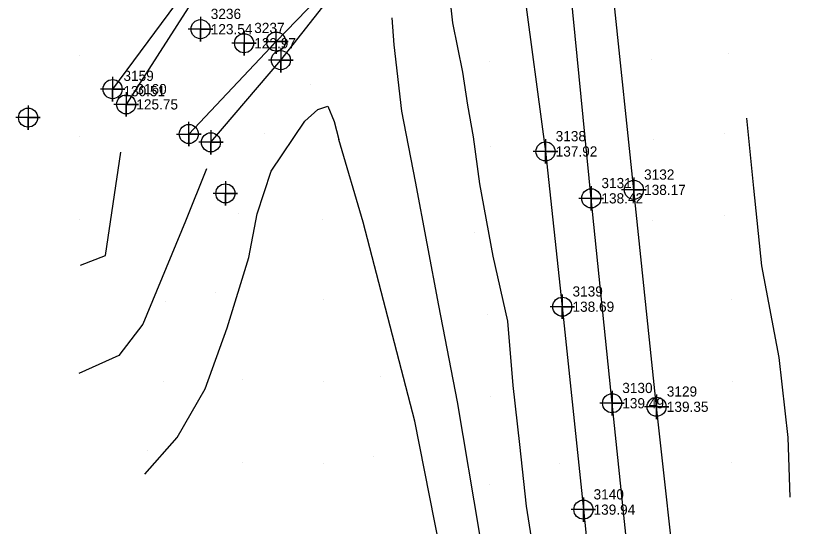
# Model space of a CAD drawing. Extents: x 2312183 to 2312663, y 819676 to 820746.
# Drawn here: x 2312350.8 to 2312544.8, y 819940.8 to 820065.9 of the extents above; entities that cross this region are included whole.
import ezdxf

# ---------------------------------------------------------------- set-up
doc = ezdxf.new("R2010")
doc.units = 0
for name, color, linetype in [('Exist DTM Breakline', 7, 'Continuous'), ('Exist DTM Breakline Cogo Point CELL', 7, 'Continuous'), ('Exist DTM Crownline', 7, 'Continuous'), ('Exist DTM Crownline Cogo Elevation', 7, 'Continuous'), ('Exist DTM Crownline Cogo Number', 7, 'Continuous'), ('Exist DTM Crownline Cogo Point CELL', 7, 'Continuous'), ('Exist DTM Regular Point CELL', 7, 'Continuous'), ('Exist DTM Regular Point Cogo Elevation', 7, 'Continuous'), ('Exist DTM Regular Point Cogo Number', 7, 'Continuous'), ('Exist DTM Regular Point Underwater CELL', 7, 'Continuous'), ('Exist DTM Regular Point Underwater Cogo Elevation', 7, 'Continuous'), ('Exist DTM Regular Point Underwater Cogo Number', 7, 'Continuous'), ('Exist Hydro Stream or Body of Water', 7, 'Continuous'), ('Exist Hydro Stream or Body of Water Cogo Point CELL', 7, 'Continuous'), ('Exist Roads EOP', 7, 'Continuous'), ('Exist Roads EOP Cogo Elevation', 7, 'Continuous'), ('Exist Roads EOP Cogo Number', 7, 'Continuous'), ('Exist Roads EOP Cogo Point CELL', 7, 'Continuous'), ('PH Exist DTM Breakline', 7, 'Continuous'), ('PH Exist DTM Point', 7, 'Continuous')]:
    doc.layers.add(name, color=color, linetype=linetype)

msp = doc.modelspace()

# ---------------------------------------------------------------- linework, layer by layer
at = {"layer": 'Exist DTM Breakline'}
for points in [[(2312398.6, 820034.89), (2312415.76, 820055.03), (2312429.05, 820071.99), (2312440.81, 820088.6), (2312469.05, 820107.68)], [(2312403.71, 820087.46), (2312374.49, 820047.93)]]:
    msp.add_lwpolyline(points, dxfattribs=at)
at = {"layer": 'Exist DTM Breakline Cogo Point CELL'}
for points in [[(2312415.76, 820058.03), (2312415.76, 820052.03), (2312415.76, 820055.03), (2312418.76, 820055.03), (2312412.76, 820055.03)], [(2312398.6, 820037.89), (2312398.6, 820031.89), (2312398.6, 820034.89), (2312401.6, 820034.89), (2312395.6, 820034.89)]]:
    msp.add_lwpolyline(points, dxfattribs=at)
for centre in [(2312415.76, 820055.03), (2312398.6, 820034.89)]:
    msp.add_circle(centre, 2.34, dxfattribs=at)
at = {"layer": 'Exist DTM Crownline'}
msp.add_lwpolyline([(2312507.73, 819871.39), (2312502.62, 819916.87), (2312496.97, 819970.94), (2312491.86, 820021.16), (2312483.41, 820106.75)], dxfattribs=at)
at = {"layer": 'Exist DTM Crownline Cogo Point CELL'}
for points in [[(2312491.86, 820024.16), (2312491.86, 820018.16), (2312491.86, 820021.16), (2312494.86, 820021.16), (2312488.86, 820021.16)], [(2312491.86, 820024.16), (2312491.86, 820018.16), (2312491.86, 820021.16), (2312494.86, 820021.16), (2312488.86, 820021.16)], [(2312496.97, 819973.94), (2312496.97, 819967.94), (2312496.97, 819970.94), (2312499.97, 819970.94), (2312493.97, 819970.94)], [(2312496.97, 819973.94), (2312496.97, 819967.94), (2312496.97, 819970.94), (2312499.97, 819970.94), (2312493.97, 819970.94)]]:
    msp.add_lwpolyline(points, dxfattribs=at)
for centre in [(2312491.86, 820021.16), (2312491.86, 820021.16), (2312496.97, 819970.94), (2312496.97, 819970.94)]:
    msp.add_circle(centre, 2.34, dxfattribs=at)
at = {"layer": 'Exist DTM Regular Point CELL'}
for points in [[(2312374.49, 820050.93), (2312374.49, 820044.93), (2312374.49, 820047.93), (2312377.49, 820047.93), (2312371.49, 820047.93)], [(2312377.81, 820047.19), (2312377.81, 820041.19), (2312377.81, 820044.19), (2312380.81, 820044.19), (2312374.81, 820044.19)], [(2312377.81, 820047.19), (2312377.81, 820041.19), (2312377.81, 820044.19), (2312380.81, 820044.19), (2312374.81, 820044.19)], [(2312353.76, 820043.94), (2312353.76, 820037.94), (2312353.76, 820040.94), (2312356.76, 820040.94), (2312350.76, 820040.94)], [(2312402.14, 820025.38), (2312402.14, 820019.38), (2312402.14, 820022.38), (2312405.14, 820022.38), (2312399.14, 820022.38)]]:
    msp.add_lwpolyline(points, dxfattribs=at)
for centre in [(2312374.49, 820047.93), (2312377.81, 820044.19), (2312377.81, 820044.19), (2312353.76, 820040.94), (2312402.14, 820022.38)]:
    msp.add_circle(centre, 2.34, dxfattribs=at)
at = {"layer": 'Exist DTM Regular Point Underwater CELL'}
for points in [[(2312396.06, 820065.62), (2312396.06, 820059.62), (2312396.06, 820062.62), (2312399.06, 820062.62), (2312393.06, 820062.62)], [(2312406.72, 820062.18), (2312406.72, 820056.18), (2312406.72, 820059.18), (2312409.72, 820059.18), (2312403.72, 820059.18)]]:
    msp.add_lwpolyline(points, dxfattribs=at)
for centre in [(2312396.06, 820062.62), (2312406.72, 820059.18)]:
    msp.add_circle(centre, 2.34, dxfattribs=at)
at = {"layer": 'Exist Hydro Stream or Body of Water'}
for points in [[(2312393.18, 820036.93), (2312414.57, 820059.59), (2312427.23, 820072.7), (2312438.05, 820092.67), (2312468.54, 820109.59), (2312503.07, 820119.67), (2312550.88, 820117.01)], [(2312405.41, 820087.34), (2312377.81, 820044.19)]]:
    msp.add_lwpolyline(points, dxfattribs=at)
at = {"layer": 'Exist Hydro Stream or Body of Water Cogo Point CELL'}
for points in [[(2312411.57, 820059.59), (2312417.57, 820059.59), (2312414.57, 820059.59), (2312414.57, 820056.59), (2312414.57, 820062.59)], [(2312390.18, 820036.93), (2312396.18, 820036.93), (2312393.18, 820036.93), (2312393.18, 820033.93), (2312393.18, 820039.93)]]:
    msp.add_lwpolyline(points, dxfattribs=at)
for centre in [(2312414.57, 820059.59), (2312393.18, 820036.93)]:
    msp.add_circle(centre, 2.34, dxfattribs=at)
at = {"layer": 'Exist Roads EOP'}
msp.add_lwpolyline([(2312518.41, 819872.35), (2312513.32, 819920.69), (2312507.89, 819970.07), (2312502.32, 820023.24), (2312497.48, 820069.17), (2312493.43, 820108.42), (2312471.82, 820106.17), (2312475.2, 820073.59), (2312480.64, 820032.66), (2312484.77, 819994.6), (2312489.93, 819944.86), (2312494.64, 819899.39), (2312498.09, 819869.36)], dxfattribs=at)
at = {"layer": 'Exist Roads EOP Cogo Point CELL'}
for points in [[(2312480.64, 820035.66), (2312480.64, 820029.66), (2312480.64, 820032.66), (2312483.64, 820032.66), (2312477.64, 820032.66)], [(2312480.64, 820035.66), (2312480.64, 820029.66), (2312480.64, 820032.66), (2312483.64, 820032.66), (2312477.64, 820032.66)], [(2312480.64, 820035.66), (2312480.64, 820029.66), (2312480.64, 820032.66), (2312483.64, 820032.66), (2312477.64, 820032.66)], [(2312502.32, 820026.24), (2312502.32, 820020.24), (2312502.32, 820023.24), (2312505.32, 820023.24), (2312499.32, 820023.24)], [(2312502.32, 820026.24), (2312502.32, 820020.24), (2312502.32, 820023.24), (2312505.32, 820023.24), (2312499.32, 820023.24)], [(2312502.32, 820026.24), (2312502.32, 820020.24), (2312502.32, 820023.24), (2312505.32, 820023.24), (2312499.32, 820023.24)], [(2312484.77, 819997.6), (2312484.77, 819991.6), (2312484.77, 819994.6), (2312487.77, 819994.6), (2312481.77, 819994.6)], [(2312484.77, 819997.6), (2312484.77, 819991.6), (2312484.77, 819994.6), (2312487.77, 819994.6), (2312481.77, 819994.6)], [(2312484.77, 819997.6), (2312484.77, 819991.6), (2312484.77, 819994.6), (2312487.77, 819994.6), (2312481.77, 819994.6)], [(2312507.89, 819973.07), (2312507.89, 819967.07), (2312507.89, 819970.07), (2312510.89, 819970.07), (2312504.89, 819970.07)], [(2312507.89, 819973.07), (2312507.89, 819967.07), (2312507.89, 819970.07), (2312510.89, 819970.07), (2312504.89, 819970.07)], [(2312507.89, 819973.07), (2312507.89, 819967.07), (2312507.89, 819970.07), (2312510.89, 819970.07), (2312504.89, 819970.07)], [(2312489.93, 819947.86), (2312489.93, 819941.86), (2312489.93, 819944.86), (2312492.93, 819944.86), (2312486.93, 819944.86)], [(2312489.93, 819947.86), (2312489.93, 819941.86), (2312489.93, 819944.86), (2312492.93, 819944.86), (2312486.93, 819944.86)], [(2312489.93, 819947.86), (2312489.93, 819941.86), (2312489.93, 819944.86), (2312492.93, 819944.86), (2312486.93, 819944.86)]]:
    msp.add_lwpolyline(points, dxfattribs=at)
for centre in [(2312480.64, 820032.66), (2312480.64, 820032.66), (2312480.64, 820032.66), (2312502.32, 820023.24), (2312502.32, 820023.24), (2312502.32, 820023.24), (2312484.77, 819994.6), (2312484.77, 819994.6), (2312484.77, 819994.6), (2312507.89, 819970.07), (2312507.89, 819970.07), (2312507.89, 819970.07), (2312489.93, 819944.86), (2312489.93, 819944.86), (2312489.93, 819944.86)]:
    msp.add_circle(centre, 2.34, dxfattribs=at)
at = {"layer": 'PH Exist DTM Breakline'}
for points in [[(2312468.58, 820100.89), (2312463.34, 820086.29), (2312460.04, 820080.12), (2312456.79, 820073.77), (2312457.87, 820064.19), (2312460.28, 820052.1), (2312461.5, 820043.97), (2312462.94, 820036.24), (2312464.44, 820024.72), (2312467.71, 820007.01), (2312471.31, 819991.07), (2312472.67, 819975.28), (2312474.3, 819960.8), (2312475.94, 819945.72), (2312478.04, 819932.21)], [(2312503.34, 819702.08), (2312502.81, 819704.79), (2312500.39, 819723.23), (2312497.46, 819741.87), (2312495.03, 819754.19), (2312492.55, 819770.03), (2312490.74, 819779.57), (2312489.87, 819790), (2312488.08, 819803.96), (2312484.99, 819820.88), (2312481.53, 819848.23), (2312477.71, 819873.12), (2312474.2, 819891.66), (2312471.62, 819909.28), (2312467.7, 819926.63), (2312464.56, 819938.8), (2312459.08, 819971.31), (2312454.5, 819994.88), (2312448.74, 820025.26), (2312445.38, 820042.56), (2312443.53, 820058.78), (2312443.06, 820065.38)], [(2312382.4, 819953.56), (2312390.33, 819962.54), (2312397.16, 819974.44), (2312402.55, 819989.4), (2312407.91, 820006.62), (2312409.93, 820017.36), (2312413.41, 820027.8), (2312421.61, 820040.08), (2312424.8, 820042.93), (2312427.25, 820043.72), (2312428.81, 820040), (2312429.94, 820035.61)], [(2312529.92, 820040.8), (2312531.69, 820023.68), (2312533.6, 820004.6), (2312537.86, 819982.13), (2312540.06, 819962.58), (2312540.58, 819947.95)], [(2312458.55, 819915.83), (2312454.67, 819935.89), (2312448.61, 819966.53), (2312435.94, 820015.33), (2312429.94, 820035.61)], [(2312366.61, 820004.77), (2312372.79, 820007.19), (2312376.53, 820032.49)], [(2312397.51, 820028.38), (2312392.33, 820015.59), (2312381.92, 819990.32), (2312376.04, 819982.62), (2312366.19, 819978.26)]]:
    msp.add_lwpolyline(points, dxfattribs=at)
at = {"layer": 'PH Exist DTM Point'}
for p, q in [((2312366.31, 820056.29), (2312366.31, 820056.29)), ((2312525.5, 820056.71), (2312525.5, 820056.71)), ((2312466.8, 820054.74), (2312466.8, 820054.74)), ((2312506.68, 820055.15), (2312506.68, 820055.15)), ((2312423.1, 820048.97), (2312423.1, 820048.97)), ((2312411.71, 820037.05), (2312411.71, 820037.05)), ((2312524.49, 820037.12), (2312524.49, 820037.12)), ((2312366.27, 820036.43), (2312366.27, 820036.43)), ((2312507.11, 820035.68), (2312507.11, 820035.68)), ((2312467.08, 820033.88), (2312467.08, 820033.88)), ((2312405.27, 820017.52), (2312405.27, 820017.52)), ((2312366.32, 820015.99), (2312366.32, 820015.99)), ((2312426.01, 820016.08), (2312426.01, 820016.08)), ((2312506.82, 820015.81), (2312506.82, 820015.81)), ((2312524.58, 820016.94), (2312524.58, 820016.94)), ((2312463.26, 820012.78), (2312463.26, 820012.78)), ((2312399.8, 819998.08), (2312399.8, 819998.08)), ((2312387.52, 819995.99), (2312387.52, 819995.99)), ((2312426.32, 819996.25), (2312426.32, 819996.25)), ((2312526.33, 819996.25), (2312526.33, 819996.25)), ((2312466.53, 819992.77), (2312466.53, 819992.77)), ((2312406.36, 819976.68), (2312406.36, 819976.68)), ((2312440.27, 819977.58), (2312440.27, 819977.58)), ((2312387.06, 819976.32), (2312387.06, 819976.32)), ((2312426.32, 819976.25), (2312426.32, 819976.25)), ((2312526.44, 819976.28), (2312526.44, 819976.28)), ((2312467.26, 819972.56), (2312467.26, 819972.56)), ((2312383.13, 819959.45), (2312383.13, 819959.45)), ((2312438.51, 819957.8), (2312438.51, 819957.8)), ((2312406.27, 819956.53), (2312406.27, 819956.53)), ((2312426.26, 819956.23), (2312426.26, 819956.23)), ((2312483.98, 819956.28), (2312483.98, 819956.28)), ((2312526.33, 819956.35), (2312526.33, 819956.35)), ((2312467.01, 819951.01), (2312467.01, 819951.01))]:
    msp.add_line(p, q, dxfattribs=at)

# ---------------------------------------------------------------- texts
at = {"layer": 'Exist DTM Crownline Cogo Elevation'}
for s, p in [('138.42', (2312494.36, 820019.91)), ('139.49', (2312499.47, 819969.69))]:
    msp.add_text(s, height=2.5, dxfattribs=at).set_placement(p)
at = {"layer": 'Exist DTM Crownline Cogo Number'}
for s, p in [('3131', (2312494.36, 820023.66)), ('3130', (2312499.47, 819973.44))]:
    msp.add_text(s, height=2.5, dxfattribs=at).set_placement(p)
at = {"layer": 'Exist DTM Regular Point Cogo Elevation'}
for s, p in [('130.51', (2312377.15, 820046.19)), ('125.75', (2312380.31, 820042.94))]:
    msp.add_text(s, height=2.5, dxfattribs=at).set_placement(p)
at = {"layer": 'Exist DTM Regular Point Cogo Number'}
for s, p in [('3159', (2312377.15, 820049.94)), ('3160', (2312380.31, 820046.69))]:
    msp.add_text(s, height=2.5, dxfattribs=at).set_placement(p)
at = {"layer": 'Exist DTM Regular Point Underwater Cogo Elevation'}
for s, p in [('123.54', (2312398.56, 820061.37)), ('122.97', (2312409.22, 820057.93))]:
    msp.add_text(s, height=2.5, dxfattribs=at).set_placement(p)
at = {"layer": 'Exist DTM Regular Point Underwater Cogo Number'}
for s, p in [('3236', (2312398.56, 820065.12)), ('3237', (2312409.22, 820061.68))]:
    msp.add_text(s, height=2.5, dxfattribs=at).set_placement(p)
at = {"layer": 'Exist Roads EOP Cogo Elevation'}
for s, p in [('137.92', (2312483.14, 820031.41)), ('138.17', (2312504.82, 820021.99)), ('138.69', (2312487.27, 819993.35)), ('139.35', (2312510.39, 819968.82)), ('139.94', (2312492.43, 819943.61))]:
    msp.add_text(s, height=2.5, dxfattribs=at).set_placement(p)
at = {"layer": 'Exist Roads EOP Cogo Number'}
for s, p in [('3138', (2312483.14, 820035.16)), ('3132', (2312504.82, 820025.74)), ('3139', (2312487.27, 819997.1)), ('3129', (2312510.39, 819972.57)), ('3140', (2312492.43, 819947.36))]:
    msp.add_text(s, height=2.5, dxfattribs=at).set_placement(p)

doc.saveas('drawing.dxf')
